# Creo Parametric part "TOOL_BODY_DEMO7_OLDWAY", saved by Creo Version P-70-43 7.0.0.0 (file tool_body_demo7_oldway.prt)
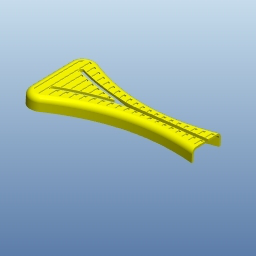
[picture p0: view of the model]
Units: millimeter Kilogram Sec (mmKs); MM, KILOGRAM, SECS
Materials in the file: NO_MATERIAL

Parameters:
  TITLE = "TITLE PARAMETER"
  DESCRIPTION = "DESCRIPTION PARAMETER"
  PART_NUMBER = "PARAMETER"
  DRAWN_BY = "PARAMETER"
  PROI_CREATED_BY = "nswadmin"
  PROI_CREATED_ON = "7/20/2004 11:43:31 AM"
  PROI_LOCATION = "Root Folder/Standards/Start Parts"
  AGILE_ITEM_NUMBER = "N/A"
  PTC_WM_ITERATION = "0"
  PTC_WM_VERSION = ".0"
  PTC_WM_CREATED_ON = "28-Aug-19 11:57:51 AM"
  PTC_WM_MODIFIED_ON = "28-Aug-19 11:57:51 AM"
  CATALOG_NUMBER = "XX####"

Created from: IN_ABSOLUTE_ACCURACY_MITG-BLDR.PRT

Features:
  1. datum plane "SIDE"
  2. datum plane "TOP"
  3. datum plane "FRONT"
  4. coordinate system
  5. extrusion "Extrude 1"
  6. round "Round 1"
  7. round "Round 3"
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
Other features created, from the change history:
  extruded cut "Extrude 2"
  round "Round 2"
  shell "Shell 1" (2 times)
  extruded cut "Extrude 3"
  extrusion "Extrude 4"
  chamfer "Chamfer 1"
  feature "Copy Geometry id 3942"
  extruded cut "Extrude 24"
  group "LOCAL_GROUP_20"
  feature "Body Subtract 1"
  extruded cut "Extrude 32"
  feature "Copy 1" (2 times)
  extruded cut "Extrude 25"
  feature "Merge 1"
  datum plane "DTM1"
  feature "Extend 1"
  feature "Copy 2" (2 times)
  feature "Merge 2"
  feature "Merge 3"
  feature "Merge 4"
  patch "Solidify 1"

Other named items: CS0, BACK_ALL, BOTTOM_ALL, FRONT_ALL, LEFT_ALL, RIGHT_ALL, TOP_ALL, ANNOT_LAYER_STATE0001, ANNOT_LAYER_STATE0002, ANNOT_LAYER_STATE0003, ANNOT_LAYER_STATE0004, ANNOT_LAYER_STATE0005, ANNOT_LAYER_STATE0006

Layers: AXES, COPY_GEOMETRY, COSMETICS, DATUM_CSYS, DATUM_CURVES, DATUM_PLANES, DATUM_POINTS, SURFACES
